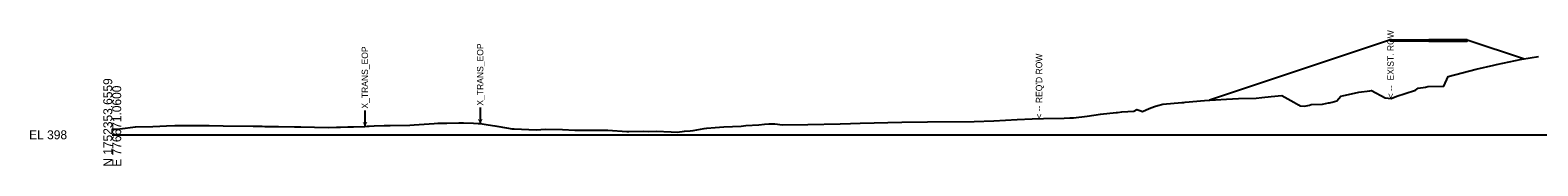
# Model space of a CAD drawing. Extents: x 776426 to 854588, y 1736205 to 1756790.
# Drawn here: x 805845.1 to 806316.9, y 1752705.1 to 1752747.5 of the extents above; entities that cross this region are included whole.
import ezdxf

# ---------------------------------------------------------------- set-up
doc = ezdxf.new("R2010")
doc.units = 0
for name, color, linetype in [('DTM CONTOURS_MAJOR_TX', 7, 'Continuous'), ('DTM_X_FLOW_ARROWS', 7, 'Continuous'), ('X_TRANS_EOP', 7, 'Continuous'), ('XS_P_DR_GRAVEL', 7, 'Continuous'), ('XS_P_GROUND', 7, 'Continuous'), ('XS_P_ROW', 7, 'Continuous'), ('XS_X_PAVEMENT', 7, 'Continuous'), ('XS_X_ROW', 7, 'Continuous')]:
    doc.layers.add(name, color=color, linetype=linetype)

msp = doc.modelspace()

# ---------------------------------------------------------------- linework, layer by layer
at = {"layer": 'DTM CONTOURS_MAJOR_TX'}
msp.add_line((805870.79, 1752714.76), (806370.79, 1752714.76), dxfattribs=at)
at = {"layer": 'DTM_X_FLOW_ARROWS'}
msp.add_lwpolyline([(805870.79, 1752716.55), (805872.21, 1752716.54), (805873.18, 1752716.61), (805878.1, 1752717.23), (805883.45, 1752717.34), (805885.72, 1752717.46), (805887.79, 1752717.54), (805890.39, 1752717.62), (805894.58, 1752717.67), (805896.88, 1752717.64), (805901.1, 1752717.66), (805905.48, 1752717.52), (805914.89, 1752717.48), (805917.73, 1752717.41), (805918.52, 1752717.35), (805922.86, 1752717.34), (805927.84, 1752717.24), (805929.8, 1752717.24), (805938.37, 1752717.08), (805940.95, 1752717.1), (805942.18, 1752717.14), (805944.53, 1752717.23), (805946.29, 1752717.21), (805949.82, 1752717.38), (805950.54, 1752717.41), (805951.18, 1752717.42), (805952.75, 1752717.53), (805955.84, 1752717.66), (805957.79, 1752717.69), (805963.93, 1752717.8), (805965.24, 1752717.87), (805971.57, 1752718.28), (805972.69, 1752718.39), (805975.5, 1752718.44), (805979.25, 1752718.51), (805980.74, 1752718.48), (805983.78, 1752718.38), (805985.3, 1752718.34), (805985.9, 1752718.31), (805988.44, 1752717.89), (805990.48, 1752717.58), (805994.76, 1752716.82), (805995.31, 1752716.74), (805995.85, 1752716.67), (805996.54, 1752716.62), (806003.42, 1752716.33), (806006.4, 1752716.48), (806011.65, 1752716.47), (806015.58, 1752716.23), (806024.08, 1752716.16), (806025.83, 1752716.16), (806031.83, 1752715.82), (806032.44, 1752715.8), (806037.11, 1752715.9), (806038.53, 1752715.8), (806040.97, 1752715.86), (806045.67, 1752715.65), (806047.51, 1752715.6), (806049.86, 1752715.9), (806051.65, 1752716.02), (806052.6, 1752716.15), (806056.02, 1752716.76), (806056.83, 1752716.87), (806059.43, 1752717.09), (806062.2, 1752717.21), (806067.55, 1752717.51), (806069.04, 1752717.62), (806073.09, 1752717.91), (806074.92, 1752718.12), (806076.24, 1752718.22), (806077.48, 1752718.24), (806078.09, 1752718.21), (806080.57, 1752717.85), (806088.42, 1752717.94), (806098.61, 1752718.15), (806101.78, 1752718.28), (806104.81, 1752718.38), (806117.87, 1752718.75), (806125.93, 1752718.82), (806140.48, 1752718.96), (806146.62, 1752719.16), (806153.97, 1752719.57), (806158.66, 1752719.79), (806162.24, 1752719.85), (806168.71, 1752719.98), (806170.44, 1752720.02), (806171.59, 1752720.1), (806175.86, 1752720.64), (806180.01, 1752721.19), (806184.91, 1752721.72), (806185.39, 1752721.72), (806186.67, 1752721.92), (806190.51, 1752722.18), (806191.41, 1752722.66), (806192.32, 1752722.36), (806193.14, 1752722.08), (806195.28, 1752722.94), (806196.97, 1752723.66), (806197.92, 1752723.88), (806199.51, 1752724.33), (806205.46, 1752724.84), (806206.1, 1752724.88), (806206.52, 1752724.93), (806212.54, 1752725.54), (806219.46, 1752725.91), (806223.21, 1752726.11), (806228.69, 1752726.21), (806230.5, 1752726.43), (806233.4, 1752726.72), (806236.75, 1752727.07), (806240.57, 1752724.94), (806241.99, 1752724.1), (806242.44, 1752723.86), (806243.9, 1752723.75), (806245.47, 1752724.06), (806245.99, 1752724.28), (806249.45, 1752724.39), (806251.41, 1752724.72), (806251.72, 1752724.75), (806252.52, 1752725), (806253.98, 1752725.42), (806255.22, 1752726.83), (806256.19, 1752727.07), (806260.45, 1752728.04), (806260.84, 1752728.15), (806264.27, 1752728.5), (806264.87, 1752728.6), (806269.1, 1752726.36), (806270.96, 1752726.15), (806272.76, 1752726.86), (806275.33, 1752727.7), (806278.62, 1752728.76), (806279.45, 1752729.35), (806281.73, 1752729.62), (806282.5, 1752729.88), (806287.43, 1752729.98), (806288.81, 1752733.03), (806297.56, 1752735.27), (806303.06, 1752736.52), (806303.98, 1752736.73), (806311.87, 1752738.4), (806317.1, 1752739.24)], dxfattribs=at)
at = {"layer": 'X_TRANS_EOP'}
for p, q in [((805985.9, 1752723.31), (805985.9, 1752718.31)), ((805985.9, 1752723.31), (805985.9, 1752718.31)), ((805949.82, 1752722.38), (805949.82, 1752717.38)), ((805949.82, 1752722.38), (805949.82, 1752717.38))]:
    msp.add_line(p, q, dxfattribs=at)
at = {"layer": 'XS_P_DR_GRAVEL'}
for points in [[(806282.79, 1752744.52), (806282.79, 1752744.02), (806270.79, 1752744.02), (806270.79, 1752744.52), (806282.79, 1752744.52)], [(806282.79, 1752744.52), (806282.79, 1752744.02), (806294.79, 1752744.02), (806294.79, 1752744.52), (806282.79, 1752744.52)]]:
    msp.add_lwpolyline(points, dxfattribs=at)
at = {"layer": 'XS_P_GROUND'}
for points in [[(806270.79, 1752744.52), (806214.1, 1752725.62)], [(806294.79, 1752744.52), (806312.73, 1752738.54)]]:
    msp.add_lwpolyline(points, dxfattribs=at)

# ---------------------------------------------------------------- texts
at = {"layer": 'DTM CONTOURS_MAJOR_TX'}
for s, p in [('N 1752353.6559', (805870.79, 1752704.76)), ('E 776671.0600', (805873.59, 1752704.76))]:
    msp.add_text(s, height=2.8, rotation=90, dxfattribs=at).set_placement(p)
msp.add_text('EL 398', height=2.8, dxfattribs=at).set_placement((805844.79, 1752713.36))
at = {"layer": 'XS_P_ROW'}
msp.add_text("< -- REQ'D ROW", height=2, rotation=90, dxfattribs=at).set_placement((806161.79, 1752719.83))
at = {"layer": 'XS_X_PAVEMENT'}
for p in [(805950.82, 1752717.38), (805986.9, 1752718.31)]:
    msp.add_text('< --  X_TRANS_EOP', height=2, rotation=90, dxfattribs=at).set_placement(p)
at = {"layer": 'XS_X_ROW'}
msp.add_text('< --  EXIST. ROW', height=2, rotation=90, dxfattribs=at).set_placement((806271.79, 1752726.17))

doc.saveas('drawing.dxf')
